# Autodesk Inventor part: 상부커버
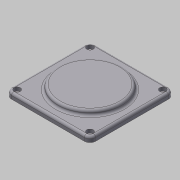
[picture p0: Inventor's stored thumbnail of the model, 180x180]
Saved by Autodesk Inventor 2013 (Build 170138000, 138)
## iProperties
Created: 2018-09
Part Number: 상부커버
Document SubType Name: Modeling
Density: 2.71 g/cm^3
Material: 알루미늄 6061
Mass: 115.614 g
Surface Area: 104.313 cm^2
Volume: 42.662 cm^3
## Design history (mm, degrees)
sketch "스케치5"
  geometry: L1 (-52.5, -52.5)-(52.5, -52.5); L2 (52.5, -52.5)-(52.5, 52.5); L3 (52.5, 52.5)-(-52.5, 52.5); L4 (-52.5, 52.5)-(-52.5, -52.5); L5 (-52.5, -52.5)-(52.5, 52.5); L6 (52.5, -52.5)-(-52.5, 52.5); 1 further point
  constraints: 12 end point, 2 midpoint, 2 parallel, 1 horizontal, 1 perpendicular
  dimensions: "d35" = 105 distance of L3.end L2.end; "d36" = 105 distance of L2.end L1.end
extrude "돌출4" new body sketch "스케치5" distance "d37" = 7; taper "d38" = 0 deg
fillet "모깎기4" dims "d39" = 7
sketch "스케치2"
  geometry: C1 r 40 at (0, 0); 2 further points
  constraints: 2 coincident, 1 centre point
  dimensions: "d4" = 80 diameter of C1
extrude "돌출3" join sketch "스케치2" distance "d5" = 6; taper "d6" = 0 deg
fillet "모깎기1" dims "d7" = 3
sketch "스케치4"
  geometry: L1 (52.5, -45.5)-(52.5, 45.5) reference; L2 (-45.5, -52.5)-(45.5, -52.5) reference; L3 (-52.5, 45.5)-(-52.5, -45.5) reference; L4 (45.5, 52.5)-(-45.5, 52.5) reference; A1 r 7 centre (45.5, 45.5) between (52.5, 45.5) and (45.5, 52.5) reference; A2 r 7 centre (45.5, -45.5) between (45.5, -52.5) and (52.5, -45.5) reference; A3 r 7 centre (-45.5, -45.5) between (-52.5, -45.5) and (-45.5, -52.5) reference; A4 r 7 centre (-45.5, 45.5) between (-45.5, 52.5) and (-52.5, 45.5) reference; 4 further points
  constraints: 4 coincident
hole "구멍3" sketch "스케치4" at (-45.5, 45.5), (-45.5, -45.5), (45.5, -45.5), (45.5, 45.5) diameter "d43" = 4.5; stored, may be unused: countersink angle "d47" = 90 deg, drill point angle "d49" = 118 deg; dims "d44" = 6, "d45" = 8, "d46" = 4.4, "d48" = 8
fillet "모깎기3" dims "d19" = 3
node "솔리드1"
node "솔리드2"
node "투영된 루프2"
